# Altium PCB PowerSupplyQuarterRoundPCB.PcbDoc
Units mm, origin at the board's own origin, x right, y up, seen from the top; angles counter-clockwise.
Board outline 60 x 60 mm, 2 copper layers (Top Layer, Bottom Layer); 23 components, 29 nets, 185 pads, 24 vias.
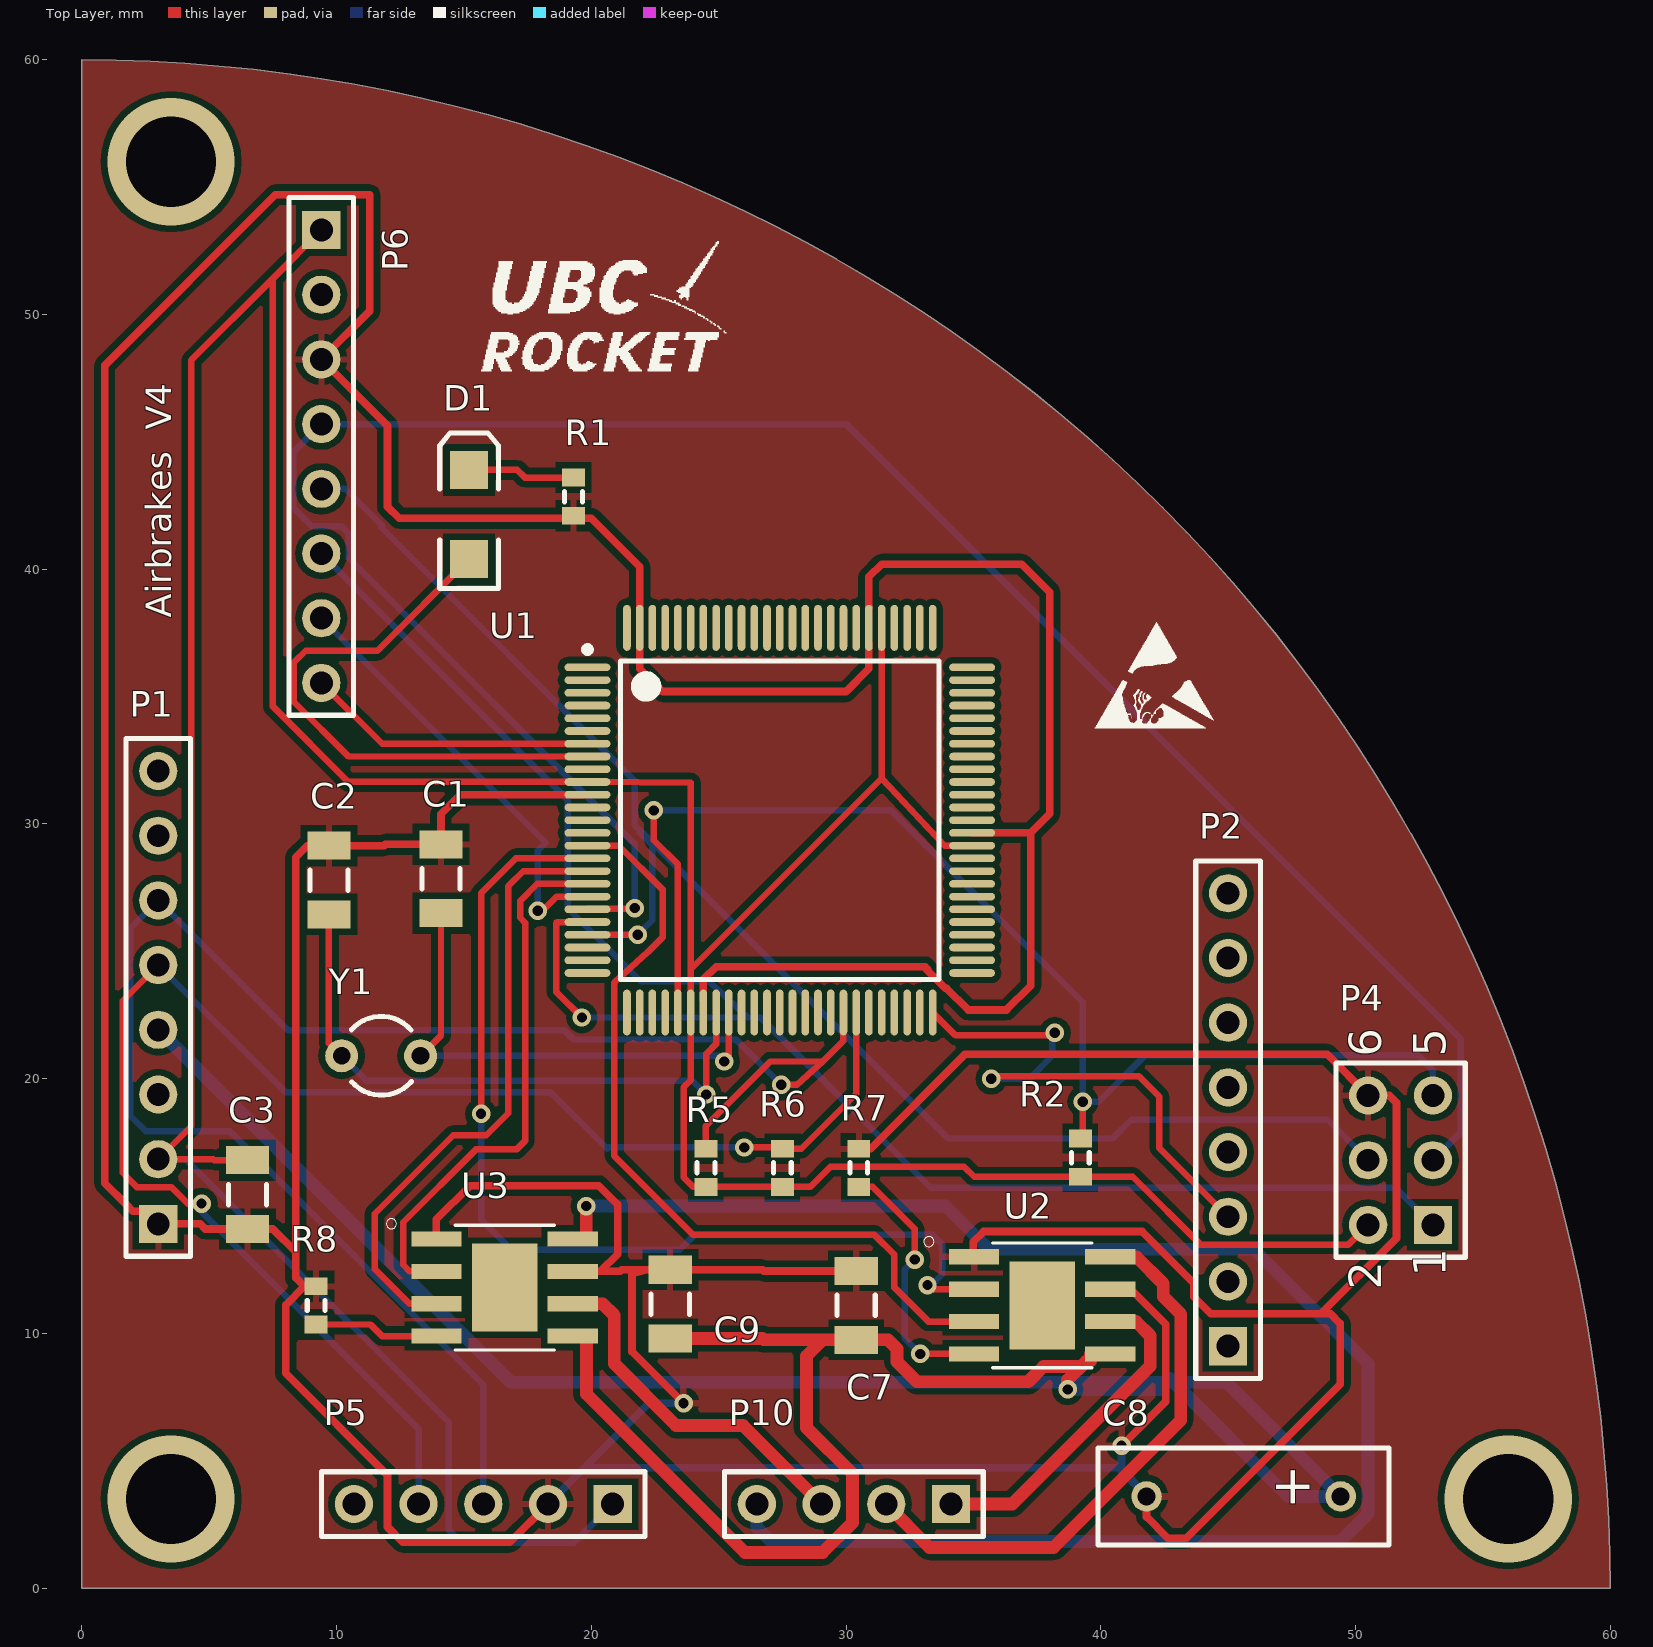
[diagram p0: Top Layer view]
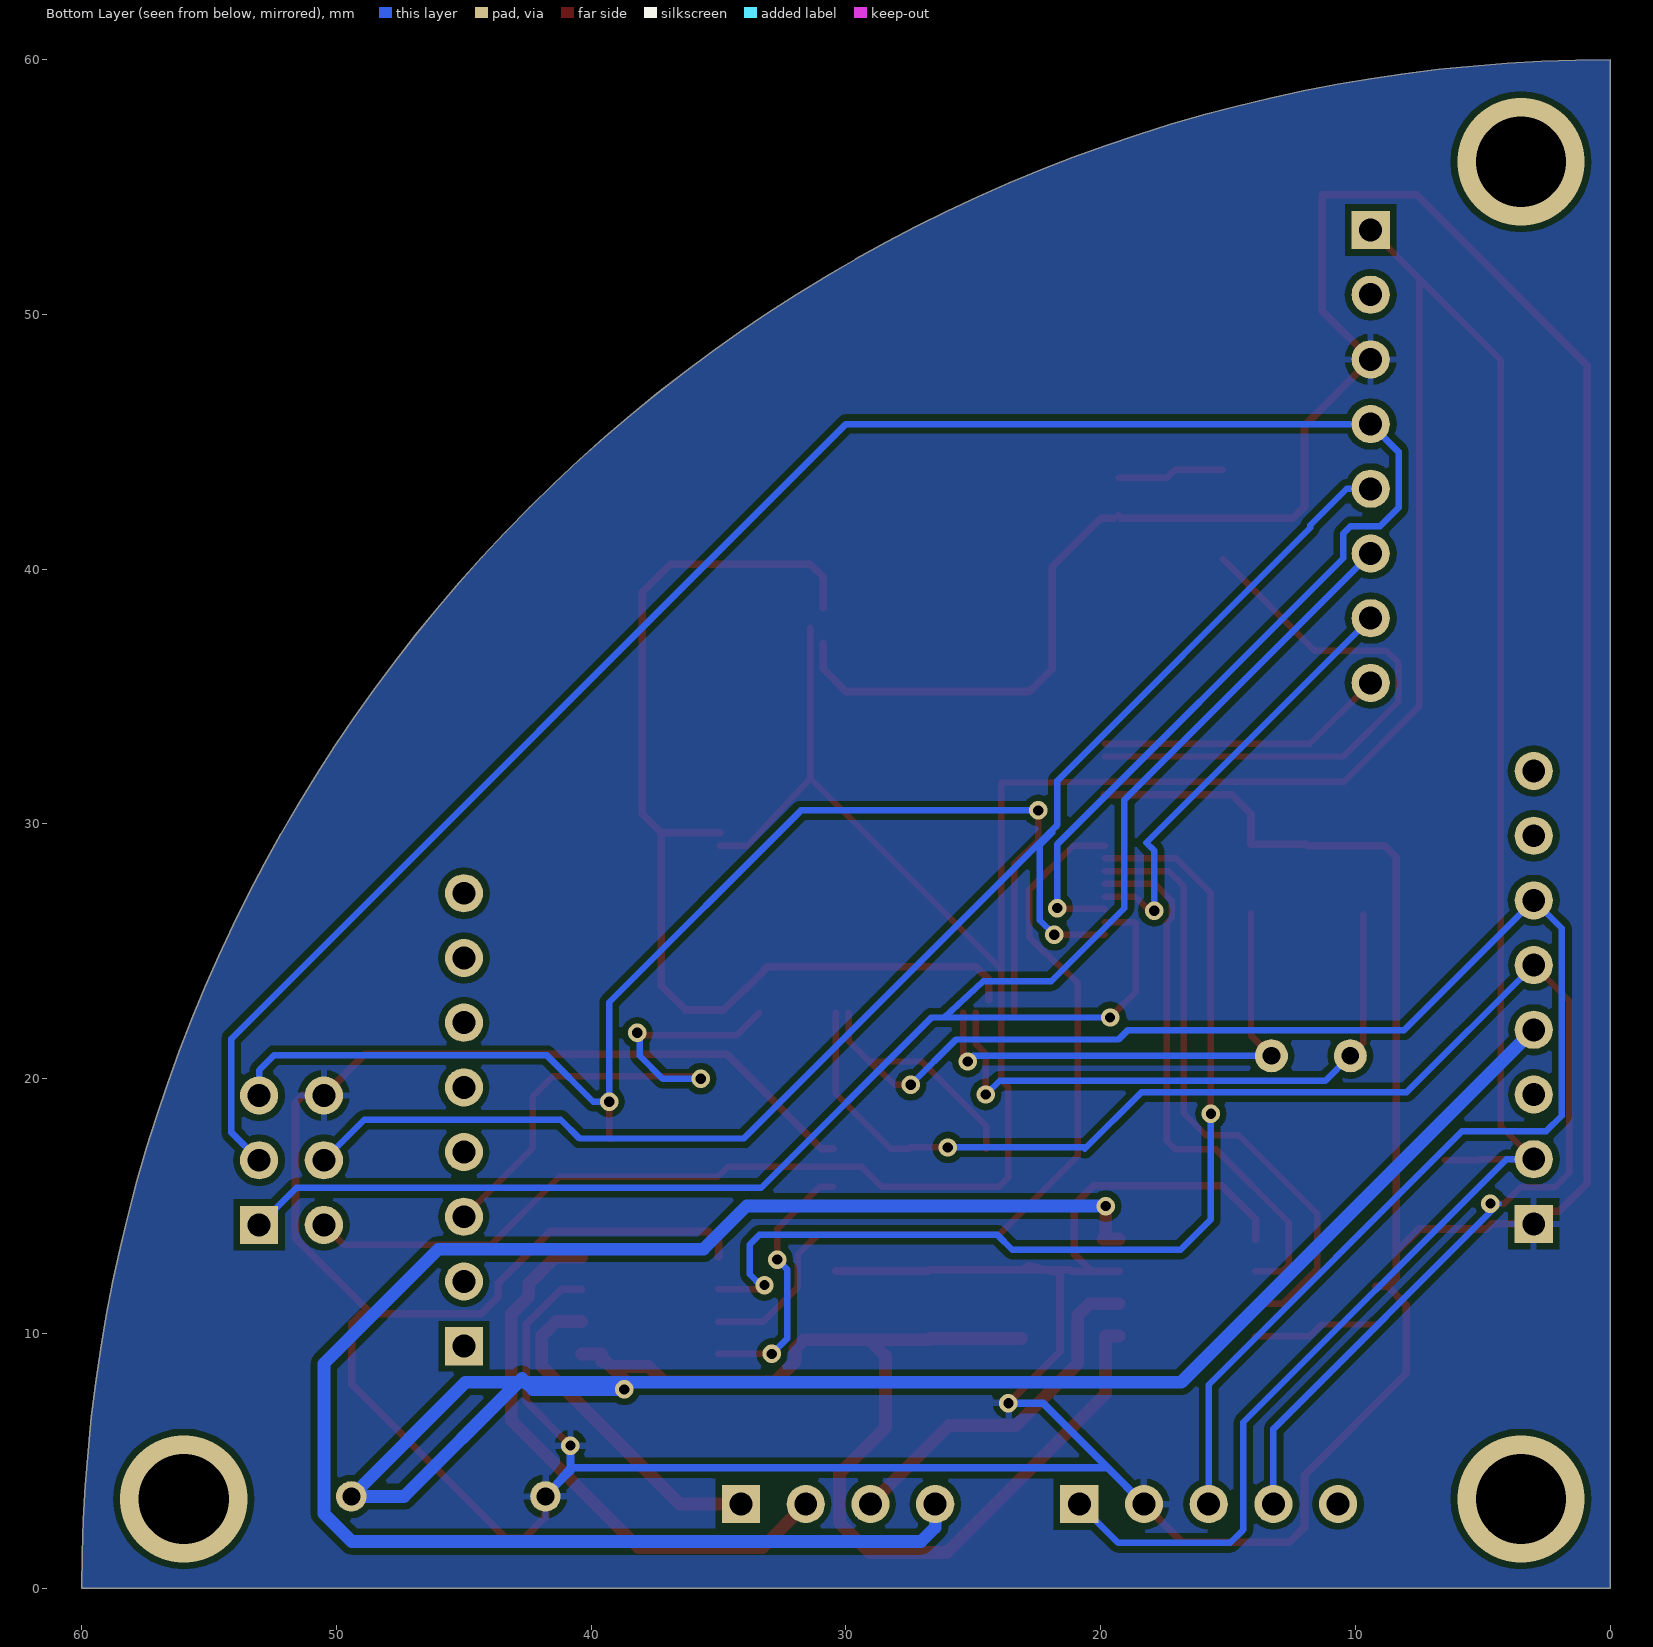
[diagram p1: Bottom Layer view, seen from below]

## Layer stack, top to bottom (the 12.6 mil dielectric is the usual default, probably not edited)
Top Solder: solder mask 0.0102, Solder Resist, Dk 3.5
Top Layer: signal copper 0.0356
Dielectric 1: dielectric 0.32, FR-4, Dk 4.8
Bottom Layer: signal copper 0.0356
Bottom Solder: solder mask 0.0102, Solder Resist, Dk 3.5

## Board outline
0,60 cw(c0,0) 60,0 0,0

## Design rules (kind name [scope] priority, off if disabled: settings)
Clearance Clearance_1 [InPolygon] p1: gap=0.254 ignorepadtopadclearanceinfootprint=FALSE except(0: Arc-Hole Track-Hole SMDPad-Hole THPad-Hole Via-Hole Fill-Hole Poly-Hole Region-Hole Text-Hole; 0.5: Arc-Arc Arc-Track Track-Track)
Clearance [All] p2: gap=0.2 ignorepadtopadclearanceinfootprint=FALSE
PolygonConnect [All] p1: connectstyle=Relief reliefconductorwidth=0.254 reliefentries=4 polygonreliefangle="90 Angle" airgapwidth=0.254
RoutingVias [All] p1: holewidth=0.406 width=0.725 viastyle="Through Hole" minholewidth=0.406 minwidth=0.725 maxholewidth=0.406 maxwidth=0.725
SolderMaskExpansion [All] p1: expansion=0.102
Width "Schematic Width Constraint_5" [InNet('OUT3')] p1: maxlimit=0.5 minlimit=0.254 preferedwidth=0.5 minimp=50.000000 maximp=50.000000 favimp=50.000000
Width "Schematic Width Constraint_4" [InNet('OUT4')] p2: maxlimit=0.5 minlimit=0.254 preferedwidth=0.5 minimp=50.000000 maximp=50.000000 favimp=50.000000
Width "Schematic Width Constraint_3" [InNet('OUT2')] p3: maxlimit=0.5 minlimit=0.254 preferedwidth=0.5 minimp=50.000000 maximp=50.000000 favimp=50.000000
Width "Schematic Width Constraint_2" [InNet('OUT1')] p4: maxlimit=0.5 minlimit=0.254 preferedwidth=0.5 minimp=50.000000 maximp=50.000000 favimp=50.000000
Width "Schematic Width Constraint_1" [InNet('+24V')] p5: maxlimit=0.5 minlimit=0.254 preferedwidth=0.5 minimp=50.000000 maximp=50.000000 favimp=50.000000
Width "Schematic Width Constraint" [InNet('GND')] p6: maxlimit=0.3 minlimit=0.254 preferedwidth=0.3 minimp=50.000000 maximp=50.000000 favimp=50.000000
Width [All] p7: maxlimit=0.254 minlimit=0.254 preferedwidth=0.254
30 further rules are at their usual default settings.

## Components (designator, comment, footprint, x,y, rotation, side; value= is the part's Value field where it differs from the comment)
C1 "Cap Semi" C1206 14.1,27.85 r270 top value=22pF
C2 "Cap Semi" C1206 9.7,27.8 r270 top value=22pF
C3 "Cap Semi" C1206 6.5,15.45 r90 top value=0.1uF
C7 "Cap Semi" C1206 30.4,11.1 r270 top value=0.1uF
C8 "Cap" RAD-0.3 45.61,3.6 r180 top value=47uF
C9 "Cap Semi" C1206 23.1,11.15 r270 top value=0.1uF
D1 "LED2" 3.2X1.6X1.1 15.2,42.15 r90 top
P1 "Header 8" HDR1X8 3,14.3 r90 top
P2 "redundancy" HDR1X8 45,9.5 r90 top
P4 "ICSP Header" HDR2X3 53.04,14.26 r90 top
P5 "Magnometer" HDR1X5 20.84,3.3 r180 top
P6 "sd card breakout" HDR1X8 9.4,53.32 r270 top
P10 "Motor output" HDR1X4 34.12,3.3 r180 top
R1 "Res3" J1-0603 19.3,42.85 r270 top value=10K
R2 "Res3" J1-0603 39.2,16.9 r90 top value=10K
R5 "Res3" J1-0603 24.5,16.5 r270 top value=10K
R6 "Res3" J1-0603 27.5,16.5 r270 top value=10K
R7 "Res3" J1-0603 30.5,16.5 r90 top value=30K
R8 "Res3" J1-0603 9.2,11.1 r90 top value=30K
U1 "ATmega2560-16AU" 100A_N 27.4,30.15 r0 top
U2 "DRV8871DDAR" SOIC127P600X170-8N 37.7,11.1 r0 top
U3 "DRV8871DDAR" SOIC127P600X170-8N 16.6,11.8 r0 top
Y1 "XTAL" R38 11.75,20.9 r90 top

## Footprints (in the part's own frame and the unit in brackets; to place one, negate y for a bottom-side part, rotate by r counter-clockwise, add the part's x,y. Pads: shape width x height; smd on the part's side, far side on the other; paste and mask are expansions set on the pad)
3.2X1.6X1.1 [mm] "SMT LED; 2 Flat Leads"
  rect 1.5x1.5 smd: 1(-1.75,0) 2(1.75,0)
  silkscreen extent -2.9,-1.15 3.2,1.15
100A_N [mm] "Thin QFP, 100-Leads, Body 14x14mm, Pitch 0.5mm, IPC Medium Density"
  oval 1.8x0.3 smd: 1(-7.55,6) 2(-7.55,5.5) 3(-7.55,5) 4(-7.55,4.5) 5(-7.55,4) 6(-7.55,3.5) 7(-7.55,3) 8(-7.55,2.5) 9(-7.55,2) 10(-7.55,1.5) 11(-7.55,1) 12(-7.55,0.5) 13(-7.55,0) 14(-7.55,-0.5) 15(-7.55,-1) 16(-7.55,-1.5) 17(-7.55,-2) 18(-7.55,-2.5) 19(-7.55,-3) 20(-7.55,-3.5) 21(-7.55,-4) 22(-7.55,-4.5) 23(-7.55,-5) 24(-7.55,-5.5) 25(-7.55,-6) 51(7.55,-6) 52(7.55,-5.5) 53(7.55,-5) 54(7.55,-4.5) 55(7.55,-4) 56(7.55,-3.5) 57(7.55,-3) 58(7.55,-2.5) 59(7.55,-2) 60(7.55,-1.5) 61(7.55,-1) 62(7.55,-0.5) 63(7.55,0) 64(7.55,0.5) 65(7.55,1) 66(7.55,1.5) 67(7.55,2) 68(7.55,2.5) 69(7.55,3) 70(7.55,3.5) 71(7.55,4) 72(7.55,4.5) 73(7.55,5) 74(7.55,5.5) 75(7.55,6)
  oval 0.3x1.8 smd: 26(-6,-7.55) 27(-5.5,-7.55) 28(-5,-7.55) 29(-4.5,-7.55) 30(-4,-7.55) 31(-3.5,-7.55) 32(-3,-7.55) 33(-2.5,-7.55) 34(-2,-7.55) 35(-1.5,-7.55) 36(-1,-7.55) 37(-0.5,-7.55) 38(0,-7.55) 39(0.5,-7.55) 40(1,-7.55) 41(1.5,-7.55) 42(2,-7.55) 43(2.5,-7.55) 44(3,-7.55) 45(3.5,-7.55) 46(4,-7.55) 47(4.5,-7.55) 48(5,-7.55) 49(5.5,-7.55) 50(6,-7.55) 76(6,7.55) 77(5.5,7.55) 78(5,7.55) 79(4.5,7.55) 80(4,7.55) 81(3.5,7.55) 82(3,7.55) 83(2.5,7.55) 84(2,7.55) 85(1.5,7.55) 86(1,7.55) 87(0.5,7.55) 88(0,7.55) 89(-0.5,7.55) 90(-1,7.55) 91(-1.5,7.55) 92(-2,7.55) 93(-2.5,7.55) 94(-3,7.55) 95(-3.5,7.55) 96(-4,7.55) 97(-4.5,7.55) 98(-5,7.55) 99(-5.5,7.55) 100(-6,7.55)
  silkscreen extent -7.67,-6.25 6.25,6.82, body extent -7,-7 7,7, height 1.2
C1206 [mm] "Chip Capacitor, Body 3.2x1.6mm, IPC High Density"
  rect 1.1x1.7 smd: 1(-1.35,0) 2(1.35,0)
  silkscreen extent -0.4,-0.75 0.4,0.75, body extent -1.7,-0.9 1.7,0.9, height 1.3
HDR1X4 [mm] "Connector; Header; 4 Position"
  rect 1.5x1.5 hole 0.9: 1(0,0)
  round 1.5 hole 0.9: 2(2.54,0) 3(5.08,0) 4(7.62,0)
  silkscreen extent -1.27,-1.27 8.89,1.27
HDR1X5 [mm] "Connector; Header; 5 Position"
  rect 1.5x1.5 hole 0.9: 1(0,0)
  round 1.5 hole 0.9: 2(2.54,0) 3(5.08,0) 4(7.62,0) 5(10.16,0)
  silkscreen extent -1.27,-1.27 11.43,1.27
HDR1X8 [mm] "Connector; Header; 8 Position"
  rect 1.5x1.5 hole 0.9: 1(0,0)
  round 1.5 hole 0.9: 2(2.54,0) 3(5.08,0) 4(7.62,0) 5(10.16,0) 6(12.7,0) 7(15.24,0) 8(17.78,0)
  silkscreen extent -1.27,-1.27 19.05,1.27
HDR2X3 [mm] "Connector; Header; 3x2 Position"
  rect 1.5x1.5 hole 0.9: 1(0,0)
  round 1.5 hole 0.9: 2(0,2.54) 3(2.54,0) 4(2.54,2.54) 5(5.08,0) 6(5.08,2.54)
  silkscreen extent -1.27,-1.27 6.35,3.81
J1-0603 [mm] "Chip Resistor, Body 1.6x0.8mm, IPC High Density"
  rect 0.7x0.9 smd: 1(-0.75,0) 2(0.75,0)
  silkscreen extent -0.2,-0.35 0.2,0.35, body extent -0.85,-0.48 0.85,0.48, height 0.9
R38 [mm] "Crystal, Thru-Hole; 2 Leads; Body 3.1 x 8.2 mm (Dia.xH)"
  round 1.3 hole 0.7: 1(0,1.55) 2(0,-1.55)
  silkscreen extent -1.55,-1.19 1.55,1.17
RAD-0.3 [mm] "Radial Cap, Thru-Hole; 2 Leads; 0.3 in Pin Spacing"
  round 1.2 hole 0.7: 1(-3.81,0) 2(3.81,0)
  silkscreen extent -5.72,-1.9 5.71,1.91
SOIC127P600X170-8N [mm]
  rect 1.97x0.6 smd: 1(-2.675,1.905) 2(-2.675,0.635) 3(-2.675,-0.635) 4(-2.675,-1.905) 5(2.675,-1.905) 6(2.675,-0.635) 7(2.675,0.635) 8(2.675,1.905)
  rect 2.58x3.45 smd: 9(0,0)
  silkscreen extent -4.64,-2.45 1.95,2.7

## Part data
C1 C2 C3 C7 C9: "Capacitor (Semiconductor SIM Model)"
C8: "Capacitor"
D1: "Typical RED, GREEN, YELLOW, AMBER GaAs LED"
P1: "Header, 8-Pin"
P2 P6: library part "Header 8", "Header, 8-Pin"
P4: library part "Header 3X2", "Header, 3-Pin, Dual row"
P5: library part "Header 5", "Header, 5-Pin"
P10: library part "Header 4", "Header, 4-Pin"
R1 R2 R5 R6 R7 R8: "Resistor"
U1: "8-bit AVR Microcontroller, 4.5-5.5V, 256KB Flash, 4KB EEPROM, 8KB SRAM, 86 GPIO pins, 100-pin TQFP, Industrial Grade (-40°C to 85°C), Pb-Free", Supplier Part Number 1=ATMEGA2560-16AU-ND
U2 U3: "3.6A Brushed DC Motor Driver with Integrated Current Sensing (PWM Ctrl) 8-SO PowerPAD -40 to 125", Package="SO-8 Texas Instruments"
Y1: "Crystal Oscillator"

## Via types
v1: diameter 0.725, hole 0.406, Top Layer to Bottom Layer, 21 vias
v2: diameter 5, hole 3.54, Top Layer to Bottom Layer, 3 vias

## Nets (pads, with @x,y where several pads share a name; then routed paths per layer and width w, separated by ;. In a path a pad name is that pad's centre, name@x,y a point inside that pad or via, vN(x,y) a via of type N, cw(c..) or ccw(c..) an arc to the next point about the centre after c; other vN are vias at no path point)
3.3V: P1.7
3V3: P1.3
5V: P1.8
+5V: C3.2 P1.2 P4.2 P5.1 P6.1 R2.1 R5.2 R6.2 U1.10 U1.31 U1.61 U1.80 | length 170
  Top Layer w0.254: C3.2 5.201,16.8 5.161,16.84 P1.2 4.293,18.133 4.293,48.213 7.5,51.42 ; P6.1 7.5,51.42 ; U1.80 31.4,31.8 ; U1.61 33.879,29.15 31.4,31.8 ; P4.2 49.727,13.487 43.917,13.487 41.254,16.15 R2.1 35.031,16.15 34.646,16.535 29.386,16.535 28.6,15.75 R6.2 25.984,15.75 R5.2 24.003,15.75 23.622,16.131 23.622,19.66 23.9,19.938 U1.31 23.9,24.3 ; 7.5,51.42 7.5,34.613 10.463,31.65 U1.10 23.9,31.626 23.9,24.3 ; 23.9,24.3 31.4,31.8
  Bottom Layer w0.254: P1.2 4.072,16.84 14.402,6.51 14.402,2.286 14.91,1.778 19.318,1.778 P5.1
+24V: C7.2 C8.1 C9.2 P1.4 U2.5 U3.5 | length 111.6
  Top Layer w0.5: U3.5 19.812,9.895 19.812,7.62 26.035,1.397 29.083,1.397 30.251,2.565 30.251,4.496 28.448,6.299 28.448,9.115 29.083,9.75 ; C9.2 26.721,9.8 26.771,9.75 29.083,9.75 ; v1(38.7,7.8) 38.7,8.169 39.44,8.909 39.44,8.915 39.225,8.7 37.754,8.7 37.154,8.1 32.791,8.1 32.001,8.89 32.001,9.398 31.649,9.75 C7.2 29.083,9.75 ; U2.5@39.446,8.915 39.6,8.915 39.6,9.195 U2.5
  Bottom Layer w0.5: P1.4 16.836,8.084 42.578,8.084 ; v1(38.7,7.8) 42.293,7.8 42.578,8.084 ; 42.578,8.084 42.723,8.23 42.868,8.084 ; 42.578,8.084 42.868,8.084 ; 42.868,8.084 47.352,3.6 C8.1 44.936,8.084 42.868,8.084
Burnout: P2.3 U1.50 | length 21.6
  Top Layer w0.254: U1.50 34.3,21.7 v1@38.3,21.7 ; v1@35.7,20.1 41.5,20.1 42.3,19.3 42.3,17.28 P2.3
  Bottom Layer w0.254: v1(35.7,20) 37.2,20 38.1,20.9 v1@38.1,21.7
  other v1: 38.2,21.8
CD: P6.8 U1.7 | length 11.4
  Top Layer w0.254: P6.8 11.79,33.15 U1.7
CS: P6.7 U1.19 | length 17.4
  Top Layer w0.254: v1(17.9,26.6) 18.091,26.6 18.641,27.15 U1.19
  Bottom Layer w0.254: P6.7 18.212,29.268 17.9,28.956 v1(17.9,26.6)
GND: C1.1 C2.1 C3.1 C7.1 C8.2 C9.1 P1.1 P4.6 P5.2 P6.3 R1.2 R7.2 R8.2 U1.11 U1.32 U1.62 U1.81 U1.99 U2.1 U2.7 U3.1 U3.7 | length 319.8
  Top Layer w0.3: 8.407,12.178 8.736,11.85 ; R8.2 8.736,11.85 ; U3.1 13.919,13.705 13.919,14.478 15.241,15.8 20.3,15.8 21.041,15.059 21.041,13.116 20.36,12.435 ; C1.1 C1.1@14.097,29.2 ; P5.2 16.8,1.8 12.6,1.8 12,2.4 12,4.434 8,8.434 8,11.114 8.736,11.85 ; U3.7 20.36,12.435 ; R1.2 19.2,42 12.458,42 12,42.458 12,45.64 P6.3 11.3,50.14 11.3,54.7 7.6,54.7 0.9,48 0.9,15.9 1.738,15.062 2,14.8 2.5,14.8 P1.1 4.648,14.3 4.848,14.1 C3.1 7.493,14.1 8.394,13.199 8.394,12.192 8.4,12.186 8.4,28.695 8.855,29.15 C2.1 11.862,29.15 11.912,29.2 C1.1@14.097,29.2 ; R1.2@19.5,42 20,42 21.9,40.1 U1.99 21.9,36.1 22.8,35.2 30,35.2 30.9,36.1 U1.81@30.9,37.1 ; U1.11 14.859,31.15 14.097,30.388 C1.1@14.097,29.2 ; v1(23.622,7.264) 21.6,9.286 21.6,12.349 22.191,12.5 ; U1.32@24.4,23.1 24.4,23.9 24.9,24.4 33.1,24.4 33.2,24.3 ; C7.1 26.771,12.45 26.721,12.5 C9.1 ; R7.2 30.966,17.25 34.671,20.955 48.885,20.955 P4.6 51.323,19.34 51.613,19.05 51.613,13.741 48.641,10.77 ; U1.81@30.9,38.5 30.9,39.7 31.4,40.2 36.9,40.2 38,39.1 38,30.4 37.25,29.65 ; 33.157,24.3 33.9,23.557 33.943,23.557 34.8,22.7 36.3,22.7 37.25,23.65 37.25,29.65 ; U1.62 37.25,29.65 ; U2.1 35.001,13.005 35.001,13.601 35.4,14 41.626,14 43.652,11.974 43.652,11.441 44.323,10.77 48.641,10.77 ; U2.7 41.173,11.735 42.547,10.362 42.547,7.327 v1(40.818,5.598) ; C8.2 41.8,2.794 42.638,1.956 43.356,1.956 49.403,8.003 49.403,10.389 49.022,10.77 48.641,10.77 ; 20.36,12.435 21.133,12.435 21.198,12.5 22.191,12.5 ; 22.191,12.5 C9.1 ; 22.191,12.5 22.826,12.662 C9.1
  Bottom Layer w0.3: P5.2 19.724,4.724 ; v1(23.622,7.264) 22.264,7.264 19.724,4.724 ; v1(40.818,5.598) 40.818,4.724 ; 19.724,4.724 40.818,4.724 ; 40.818,4.724 40.818,4.582 C8.2 40.818,4.724
IN1: U1.15 U2.3 | length 32.5
  Top Layer w0.254: U1.15 21.082,29.15 22.8,27.432 22.8,25.547 22.225,24.972 20.904,23.774 20.904,16.967 24.003,13.868 31.115,13.868 31.9,13.083 31.9,11.8 33.235,10.465 U2.3
IN2: U1.16 U2.2 | length 40.4
  Top Layer w0.254: v1(15.672,18.618) 15.672,27.278 17.043,28.65 U1.16 ; v1(33.2,11.9) 33.365,11.735 U2.2
  Bottom Layer w0.254: v1(15.672,18.618) 15.672,14.478 16.866,13.284 23.47,13.284 24.054,13.868 33.401,13.868 33.782,13.487 33.782,12.319 33.363,11.9 v1(33.2,11.9)
IN3: U1.17 U3.3 | length 24.3
  Top Layer w0.254: U3.3 12.863,11.165 11.5,12.528 11.5,14.7 14.578,17.778 15.875,17.778 16.738,18.641 16.738,27.562 17.326,28.15 U1.17
IN4: U1.18 U3.2 | length 21.6
  Top Layer w0.254: U3.2 12.878,12.435 12.613,12.7 12.613,14.366 15.47,17.223 17.067,17.223 17.4,17.556 17.4,26.125 17.21,26.314 17.21,26.979 17.882,27.65 U1.18
MISO: P4.4 P6.5 U1.22 | length 60.2
  Top Layer w0.254: U1.22 v1(21.819,25.65)
  Bottom Layer w0.254: P6.5 10.34,43.16 11.771,41.729 11.771,41.629 21.7,31.7 21.7,29.964 21.899,29.765 ; v1(21.819,25.65) 22.39,26.221 22.39,29.166 21.899,29.657 21.899,29.765 ; P4.4 48.91,18.39 41.199,18.39 40.462,17.653 34.011,17.653 21.899,29.765
MOSI: P4.1 P6.6 U1.21 | length 68.9
  Top Layer w0.254: v1(19.634,22.403) 18.618,23.419 18.618,26.111 18.657,26.15 U1.21
  Bottom Layer w0.254: P6.6 19.074,30.946 19.074,26.697 21.946,23.825 24.613,23.825 26.142,22.403 ; v1(19.634,22.403) 26.142,22.403 ; P4.1 51.577,15.723 33.325,15.723 26.645,22.403 26.142,22.403
NetC1_2: C1.2 U1.34 Y1.2 | length 19.9
  Top Layer w0.254: Y1.2 14.1,21.7 C1.2 ; v1(25.222,20.676) 25.4,20.853 U1.34
  Bottom Layer w0.254: Y1.2 24.998,20.9 v1(25.222,20.676)
NetC2_2: C2.2 U1.33 Y1.1 | length 24.1
  Top Layer w0.254: C2.2 9.7,21.4 Y1.1 ; v1(24.511,19.38) 24.511,20.972 24.9,21.361 U1.33
  Bottom Layer w0.254: Y1.1 11.177,19.923 23.968,19.923 v1(24.511,19.38)
NetD1_1: D1.1 U1.8 | length 22.5
  Top Layer w0.254: D1.1 11.605,36.805 8.788,36.805 8.323,36.339 8.323,34.798 10.471,32.65 U1.8
NetD1_2: D1.2 R1.1 | length 4.2
  Top Layer w0.254: D1.2 17.094,43.9 17.394,43.6 R1.1
NetR7_1: R7.1 U2.4 | length 10.7
  Top Layer w0.254: R7.1 31.05,15.75 32.696,14.104 32.7,14.107 v1(32.7,12.9) ; v1(32.912,9.195) U2.4
  Bottom Layer w0.254: v1(32.912,9.195) 32.3,9.807 32.3,12.5 v1(32.7,12.9) ; v1(32.7,12.9) 32.7,13.014 32.814,12.9 v1(32.7,12.9)
NetR8_1: R8.1 U3.4 | length 4.9
  Top Layer w0.254: R8.1 11.328,10.35 11.783,9.895 U3.4
OUT1: P10.1 U2.6 | length 13.1
  Top Layer w0.5: P10.1 36.53,3.3 41.947,8.717 41.947,9.906 41.388,10.465 U2.6
OUT2: P10.2 U2.8 | length 22.5
  Top Layer w0.5: P10.2 33.28,1.6 38.143,1.6 43.147,6.604 43.147,10.752 42.456,11.443 42.456,11.951 41.402,13.005 U2.8
OUT3: P10.3 U3.6 | length 14.1
  Top Layer w0.5: U3.6 20.447,11.165 20.9,10.712 20.9,8.818 23.33,6.388 25.952,6.388 P10.3
OUT4: P10.4 U3.8 | length 66.7
  Top Layer w0.5: U3.8 19.914,13.705 19.8,13.819 v1(19.8,15)
  Bottom Layer w0.5: v1(19.8,15) 33.902,15 35.592,13.31 45.999,13.31 50.495,8.814 50.495,2.921 49.403,1.829 27.051,1.829 26.5,2.38 P10.4
RESET: P4.5 R2.2 U1.30 | length 49.5
  Top Layer w0.254: v1(22.454,30.531) 22.454,29.362 23.4,28.416 U1.30 ; R2.2 39.268,17.65 39.3,17.682 v1(39.3,19.1)
  Bottom Layer w0.254: v1(22.454,30.531) 31.769,30.531 39.3,23 v1(39.3,19.1) 39.928,19.1 41.758,20.93 52.451,20.93 53.04,20.341 P4.5
SCK: P4.3 P6.4 U1.20 | length 87.5
  Top Layer w0.254: U1.20 19.873,26.673 21.673,26.673 v1(21.7,26.7)
  Bottom Layer w0.254: v1(21.7,26.7) 21.7,29.214 10.477,40.437 10.477,41.402 10.182,41.697 9.027,41.697 8.306,42.418 8.306,44.606 P6.4 30,45.7 54.127,21.573 54.127,17.887 P4.3
SCL: P1.6 P5.3 R5.1 U1.43 | length 70.1
  Top Layer w0.254: R5.1 24.486,17.25 24.486,18.136 27.026,20.676 29.083,20.676 ; v1(27.457,19.761) 28.071,19.761 29.083,20.676 ; U1.43 29.9,21.493 29.083,20.676
  Bottom Layer w0.254: P5.3 15.76,7.989 5.817,17.932 2.515,17.932 1.905,18.542 1.905,25.905 P1.6 8.105,21.895 18.948,21.895 19.304,21.539 25.679,21.539 v1(27.457,19.761)
SDA: P1.5 P5.4 R6.1 U1.44 | length 62.6
  Top Layer w0.254: P1.5 1.6,23.06 1.6,16.307 2.159,15.748 3.514,15.748 4.162,15.1 v1(4.7,15.1) ; v1(26,17.3) 27.45,17.3 R6.1 28.244,17.25 30.4,19.406 U1.44
  Bottom Layer w0.254: P1.5 7.991,19.469 18.402,19.469 20.621,17.25 20.671,17.3 v1(26,17.3) ; v1(4.7,15.1) 4.369,15.1 13.22,6.249 P5.4
pads on no net: P2.1 P2.2 P2.4 P2.5 P2.6 P2.7 P2.8 P5.5 P6.2 U1.1 U1.2 U1.3 U1.4 U1.5 U1.6 U1.9 U1.12 U1.13 U1.14 U1.23 U1.24 U1.25 U1.26 U1.27 U1.28 U1.29 U1.35 U1.36 U1.37 U1.38 U1.39 U1.40 U1.41 U1.42 U1.45 U1.46 U1.47 U1.48 U1.49 U1.51 U1.52 U1.53 U1.54 U1.55 U1.56 U1.57 U1.58 U1.59 U1.60 U1.63 U1.64 U1.65 U1.66 U1.67 U1.68 U1.69 U1.70 U1.71 U1.72 U1.73 U1.74 U1.75 U1.76 U1.77 U1.78 U1.79 U1.82 U1.83 U1.84 U1.85 U1.86 U1.87 U1.88 U1.89 U1.90 U1.91 U1.92 U1.93 U1.94 U1.95 U1.96 U1.97 U1.98 U1.100 U2.9 U3.9
copper on no net:
  other v2: 3.5,3.5 56,3.5 3.5,56

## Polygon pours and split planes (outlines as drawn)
GND on Bottom Layer "bottom" (solid, pour order 2): 0,60 cw(c0,0) 60,0 0,0
GND on Top Layer "Top Layer-No Net" (solid, pour order 3): 0,60 cw(c0,0) 60,0 0,0

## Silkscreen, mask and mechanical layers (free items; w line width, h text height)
Top Overlay:
  drawing of 26 lines, arcs and shapes, not listed
  text "Airbrakes  V4" at 3.5,38.1 h1 r90
  text "+" at 48.2,3.1 h1.52 r90
Mechanical 1:
  lines w0.254: 0,0 0,60 ; 0,0.1 60,0.1 60,2.6 ; 0,59.6 0,0.2 0.1,0.1 ; 0,59.977 cw(c0,0) 59.977,0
